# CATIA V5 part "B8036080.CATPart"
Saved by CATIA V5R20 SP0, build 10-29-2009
Part number: B8036080
Revision: 5
Definition: design
Nomenclature: B8036080
Source: made
Description: NOT SPECIFIED
Bounding box of the stored display mesh (mm): x -42.5 to 42.5, y -42.5 to 42.5, z 0 to 80
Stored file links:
  C:\Users\Utente\Desktop\3D files B803\B8036080.CATPart
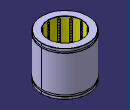
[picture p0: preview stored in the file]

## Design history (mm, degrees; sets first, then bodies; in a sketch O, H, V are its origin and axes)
Body1 "MANIFOLD_SOLID_BREP #38" (main body)
  Solid1: solid without history
Body2 "MANIFOLD_SOLID_BREP #76"
  Solid2: solid without history
Body3 "MANIFOLD_SOLID_BREP #114"
  Solid3: solid without history
Body4 "MANIFOLD_SOLID_BREP #152"
  Solid4: solid without history
Body5 "MANIFOLD_SOLID_BREP #190"
  Solid5: solid without history
Body6 "MANIFOLD_SOLID_BREP #228"
  Solid6: solid without history
Body7 "MANIFOLD_SOLID_BREP #266"
  Solid7: solid without history
Body8 "MANIFOLD_SOLID_BREP #304"
  Solid8: solid without history
Body9 "MANIFOLD_SOLID_BREP #3200"
  Solid9: solid without history
Body10 "MANIFOLD_SOLID_BREP #3238"
  Solid10: solid without history
Body11 "MANIFOLD_SOLID_BREP #3276"
  Solid11: solid without history
Body12 "MANIFOLD_SOLID_BREP #3314"
  Solid12: solid without history
Body13 "MANIFOLD_SOLID_BREP #3352"
  Solid13: solid without history
Body14 "MANIFOLD_SOLID_BREP #3390"
  Solid14: solid without history
Body15 "MANIFOLD_SOLID_BREP #3428"
  Solid15: solid without history
Body16 "MANIFOLD_SOLID_BREP #3466"
  Solid16: solid without history
Body17 "MANIFOLD_SOLID_BREP #3504"
  Solid17: solid without history
Body18 "MANIFOLD_SOLID_BREP #3542"
  Solid18: solid without history
Body19 "MANIFOLD_SOLID_BREP #3580"
  Solid19: solid without history
Body20 "MANIFOLD_SOLID_BREP #3618"
  Solid20: solid without history
Body21 "MANIFOLD_SOLID_BREP #3656"
  Solid21: solid without history
Body22 "MANIFOLD_SOLID_BREP #3694"
  Solid22: solid without history
Body23 "MANIFOLD_SOLID_BREP #3732"
  Solid23: solid without history
Body24 "MANIFOLD_SOLID_BREP #3770"
  Solid24: solid without history
Body25 "MANIFOLD_SOLID_BREP #3808"
  Solid25: solid without history
Body26 "MANIFOLD_SOLID_BREP #3846"
  Solid26: solid without history
Body27 "MANIFOLD_SOLID_BREP #3884"
  Solid27: solid without history
Body28 "MANIFOLD_SOLID_BREP #3922"
  Solid28: solid without history
Body29 "MANIFOLD_SOLID_BREP #3960"
  Solid29: solid without history
Body30 "MANIFOLD_SOLID_BREP #3998"
  Solid30: solid without history
Body31 "MANIFOLD_SOLID_BREP #4036"
  Solid31: solid without history
Body32 "MANIFOLD_SOLID_BREP #4074"
  Solid32: solid without history
Body33 "MANIFOLD_SOLID_BREP #4112"
  Solid33: solid without history
Body34 "MANIFOLD_SOLID_BREP #4150"
  Solid34: solid without history
Body35 "MANIFOLD_SOLID_BREP #4188"
  Solid35: solid without history
Body36 "MANIFOLD_SOLID_BREP #4226"
  Solid36: solid without history
Body37 "MANIFOLD_SOLID_BREP #4264"
  Solid37: solid without history
Body38 "MANIFOLD_SOLID_BREP #4302"
  Solid38: solid without history
Body39 "MANIFOLD_SOLID_BREP #4340"
  Solid39: solid without history
Body40 "MANIFOLD_SOLID_BREP #4378"
  Solid40: solid without history
Body41 "MANIFOLD_SOLID_BREP #4416"
  Solid41: solid without history
Body42 "MANIFOLD_SOLID_BREP #4454"
  Solid42: solid without history
Body43 "MANIFOLD_SOLID_BREP #4492"
  Solid43: solid without history
Body44 "MANIFOLD_SOLID_BREP #4530"
  Solid44: solid without history
Body45 "MANIFOLD_SOLID_BREP #4568"
  Solid45: solid without history
Body46 "MANIFOLD_SOLID_BREP #4606"
  Solid46: solid without history
Body47 "MANIFOLD_SOLID_BREP #4644"
  Solid47: solid without history
Body48 "MANIFOLD_SOLID_BREP #4682"
  Solid48: solid without history
Body49 "MANIFOLD_SOLID_BREP #4720"
  Solid49: solid without history
Body50 "MANIFOLD_SOLID_BREP #4758"
  Solid50: solid without history
Body51 "MANIFOLD_SOLID_BREP #4796"
  Solid51: solid without history
Body52 "MANIFOLD_SOLID_BREP #4834"
  Solid52: solid without history
Body53 "MANIFOLD_SOLID_BREP #4872"
  Solid53: solid without history
Body54 "MANIFOLD_SOLID_BREP #4910"
  Solid54: solid without history
Body55 "MANIFOLD_SOLID_BREP #4948"
  Solid55: solid without history
Body56 "MANIFOLD_SOLID_BREP #4986"
  Solid56: solid without history
Body57 "MANIFOLD_SOLID_BREP #5024"
  Solid57: solid without history
Body58 "MANIFOLD_SOLID_BREP #5062"
  Solid58: solid without history
Body59 "MANIFOLD_SOLID_BREP #5100"
  Solid59: solid without history
Body60 "MANIFOLD_SOLID_BREP #5138"
  Solid60: solid without history
Body61 "MANIFOLD_SOLID_BREP #5176"
  Solid61: solid without history
Body62 "MANIFOLD_SOLID_BREP #5214"
  Solid62: solid without history
Body63 "MANIFOLD_SOLID_BREP #5252"
  Solid63: solid without history
Body64 "MANIFOLD_SOLID_BREP #5290"
  Solid64: solid without history
Body65 "MANIFOLD_SOLID_BREP #5328"
  Solid65: solid without history
Body66 "MANIFOLD_SOLID_BREP #5366"
  Solid66: solid without history
Body67 "MANIFOLD_SOLID_BREP #5404"
  Solid67: solid without history
Body68 "MANIFOLD_SOLID_BREP #5442"
  Solid68: solid without history
Body69 "MANIFOLD_SOLID_BREP #5480"
  Solid69: solid without history
Body70 "MANIFOLD_SOLID_BREP #5518"
  Solid70: solid without history
Body71 "MANIFOLD_SOLID_BREP #5556"
  Solid71: solid without history
Body72 "MANIFOLD_SOLID_BREP #5594"
  Solid72: solid without history
Body73 "MANIFOLD_SOLID_BREP #5632"
  Solid73: solid without history
Body74 "MANIFOLD_SOLID_BREP #5670"
  Solid74: solid without history
Body75 "MANIFOLD_SOLID_BREP #5708"
  Solid75: solid without history
Body76 "MANIFOLD_SOLID_BREP #5746"
  Solid76: solid without history
Body77 "MANIFOLD_SOLID_BREP #5784"
  Solid77: solid without history
Body78 "MANIFOLD_SOLID_BREP #5822"
  Solid78: solid without history
Body79 "MANIFOLD_SOLID_BREP #5860"
  Solid79: solid without history
Body80 "MANIFOLD_SOLID_BREP #5898"
  Solid80: solid without history
Body81 "MANIFOLD_SOLID_BREP #5936"
  Solid81: solid without history
Body82 "MANIFOLD_SOLID_BREP #5974"
  Solid82: solid without history
Body83 "MANIFOLD_SOLID_BREP #6012"
  Solid83: solid without history
Body84 "MANIFOLD_SOLID_BREP #6050"
  Solid84: solid without history
Body85 "MANIFOLD_SOLID_BREP #6088"
  Solid85: solid without history
Body86 "MANIFOLD_SOLID_BREP #6126"
  Solid86: solid without history
Body87 "MANIFOLD_SOLID_BREP #6164"
  Solid87: solid without history
Body88 "MANIFOLD_SOLID_BREP #6202"
  Solid88: solid without history
Body89 "MANIFOLD_SOLID_BREP #6240"
  Solid89: solid without history
Body90 "MANIFOLD_SOLID_BREP #6278"
  Solid90: solid without history
Body91 "MANIFOLD_SOLID_BREP #6316"
  Solid91: solid without history
Body92 "MANIFOLD_SOLID_BREP #6354"
  Solid92: solid without history
Body93 "MANIFOLD_SOLID_BREP #6392"
  Solid93: solid without history
Body94 "MANIFOLD_SOLID_BREP #6430"
  Solid94: solid without history
Body95 "MANIFOLD_SOLID_BREP #6468"
  Solid95: solid without history
Body96 "MANIFOLD_SOLID_BREP #6506"
  Solid96: solid without history
Body97 "MANIFOLD_SOLID_BREP #6544"
  Solid97: solid without history
Body98 "MANIFOLD_SOLID_BREP #6582"
  Solid98: solid without history
Body99 "MANIFOLD_SOLID_BREP #6620"
  Solid99: solid without history
Body100 "MANIFOLD_SOLID_BREP #6658"
  Solid100: solid without history
Body101 "MANIFOLD_SOLID_BREP #6696"
  Solid101: solid without history
Body102 "MANIFOLD_SOLID_BREP #6734"
  Solid102: solid without history
Body103 "MANIFOLD_SOLID_BREP #6772"
  Solid103: solid without history
Body104 "MANIFOLD_SOLID_BREP #6810"
  Solid104: solid without history
Body105 "MANIFOLD_SOLID_BREP #6848"
  Solid105: solid without history
Body106 "MANIFOLD_SOLID_BREP #6886"
  Solid106: solid without history
Body107 "MANIFOLD_SOLID_BREP #6924"
  Solid107: solid without history
Body108 "MANIFOLD_SOLID_BREP #6962"
  Solid108: solid without history
Body109 "MANIFOLD_SOLID_BREP #7000"
  Solid109: solid without history
Body110 "MANIFOLD_SOLID_BREP #7038"
  Solid110: solid without history
Body111 "MANIFOLD_SOLID_BREP #7076"
  Solid111: solid without history
Body112 "MANIFOLD_SOLID_BREP #7114"
  Solid112: solid without history
Body113 "MANIFOLD_SOLID_BREP #7152"
  Solid113: solid without history
Body114 "MANIFOLD_SOLID_BREP #7190"
  Solid114: solid without history
Body115 "MANIFOLD_SOLID_BREP #7228"
  Solid115: solid without history
Body116 "MANIFOLD_SOLID_BREP #7266"
  Solid116: solid without history
Body117 "MANIFOLD_SOLID_BREP #7304"
  Solid117: solid without history
Body118 "MANIFOLD_SOLID_BREP #7342"
  Solid118: solid without history
Body119 "MANIFOLD_SOLID_BREP #7380"
  Solid119: solid without history
Body120 "MANIFOLD_SOLID_BREP #7418"
  Solid120: solid without history
Body121 "MANIFOLD_SOLID_BREP #7456"
  Solid121: solid without history
Body122 "MANIFOLD_SOLID_BREP #7494"
  Solid122: solid without history
Body123 "MANIFOLD_SOLID_BREP #7532"
  Solid123: solid without history
Body124 "MANIFOLD_SOLID_BREP #7570"
  Solid124: solid without history
Body125 "MANIFOLD_SOLID_BREP #7608"
  Solid125: solid without history
Body126 "MANIFOLD_SOLID_BREP #7646"
  Solid126: solid without history
Body127 "MANIFOLD_SOLID_BREP #7684"
  Solid127: solid without history
Body128 "MANIFOLD_SOLID_BREP #7722"
  Solid128: solid without history
Body129 "MANIFOLD_SOLID_BREP #7760"
  Solid129: solid without history
Body130 "MANIFOLD_SOLID_BREP #7798"
  Solid130: solid without history
Body131 "MANIFOLD_SOLID_BREP #7836"
  Solid131: solid without history
Body132 "MANIFOLD_SOLID_BREP #7874"
  Solid132: solid without history
Body133 "MANIFOLD_SOLID_BREP #7912"
  Solid133: solid without history
Body134 "MANIFOLD_SOLID_BREP #7950"
  Solid134: solid without history
Body135 "MANIFOLD_SOLID_BREP #7988"
  Solid135: solid without history
Body136 "MANIFOLD_SOLID_BREP #8026"
  Solid136: solid without history
Body137 "MANIFOLD_SOLID_BREP #8064"
  Solid137: solid without history
Body138 "MANIFOLD_SOLID_BREP #8102"
  Solid138: solid without history
Body139 "MANIFOLD_SOLID_BREP #8140"
  Solid139: solid without history
Body140 "MANIFOLD_SOLID_BREP #8178"
  Solid140: solid without history
Body141 "MANIFOLD_SOLID_BREP #8216"
  Solid141: solid without history
Body142 "MANIFOLD_SOLID_BREP #8254"
  Solid142: solid without history
Body143 "MANIFOLD_SOLID_BREP #8292"
  Solid143: solid without history
Body144 "MANIFOLD_SOLID_BREP #8330"
  Solid144: solid without history
Body145 "MANIFOLD_SOLID_BREP #8368"
  Solid145: solid without history
Body146 "MANIFOLD_SOLID_BREP #8406"
  Solid146: solid without history
Body147 "MANIFOLD_SOLID_BREP #8444"
  Solid147: solid without history
Body148 "MANIFOLD_SOLID_BREP #8482"
  Solid148: solid without history
Body149 "MANIFOLD_SOLID_BREP #8520"
  Solid149: solid without history
Body150 "MANIFOLD_SOLID_BREP #8558"
  Solid150: solid without history
Body151 "MANIFOLD_SOLID_BREP #8596"
  Solid151: solid without history
Body152 "MANIFOLD_SOLID_BREP #8634"
  Solid152: solid without history
Body153 "MANIFOLD_SOLID_BREP #8672"
  Solid153: solid without history
Body154 "MANIFOLD_SOLID_BREP #8710"
  Solid154: solid without history
Body155 "MANIFOLD_SOLID_BREP #8748"
  Solid155: solid without history
Body156 "MANIFOLD_SOLID_BREP #8786"
  Solid156: solid without history
Body157 "MANIFOLD_SOLID_BREP #8824"
  Solid157: solid without history
Body158 "MANIFOLD_SOLID_BREP #8862"
  Solid158: solid without history
Body159 "MANIFOLD_SOLID_BREP #8900"
  Solid159: solid without history
Body160 "MANIFOLD_SOLID_BREP #8938"
  Solid160: solid without history
Body161 "MANIFOLD_SOLID_BREP #8976"
  Solid161: solid without history
Body162 "MANIFOLD_SOLID_BREP #9014"
  Solid162: solid without history
Body163 "MANIFOLD_SOLID_BREP #9052"
  Solid163: solid without history
Body164 "MANIFOLD_SOLID_BREP #9090"
  Solid164: solid without history
Body165 "MANIFOLD_SOLID_BREP #9128"
  Solid165: solid without history
Body166 "MANIFOLD_SOLID_BREP #9166"
  Solid166: solid without history
Body167 "MANIFOLD_SOLID_BREP #9204"
  Solid167: solid without history
Body168 "MANIFOLD_SOLID_BREP #9242"
  Solid168: solid without history
Body169 "MANIFOLD_SOLID_BREP #9280"
  Solid169: solid without history
Body170 "MANIFOLD_SOLID_BREP #9318"
  Solid170: solid without history
Body171 "MANIFOLD_SOLID_BREP #9356"
  Solid171: solid without history
Body172 "MANIFOLD_SOLID_BREP #9394"
  Solid172: solid without history
Body173 "MANIFOLD_SOLID_BREP #9432"
  Solid173: solid without history
Body174 "MANIFOLD_SOLID_BREP #9470"
  Solid174: solid without history
Body175 "MANIFOLD_SOLID_BREP #9508"
  Solid175: solid without history
Body176 "MANIFOLD_SOLID_BREP #9546"
  Solid176: solid without history
Body177 "MANIFOLD_SOLID_BREP #9584"
  Solid177: solid without history
Body178 "MANIFOLD_SOLID_BREP #9622"
  Solid178: solid without history
Body179 "MANIFOLD_SOLID_BREP #9660"
  Solid179: solid without history
Body180 "MANIFOLD_SOLID_BREP #9698"
  Solid180: solid without history
Body181 "MANIFOLD_SOLID_BREP #9736"
  Solid181: solid without history
Body182 "MANIFOLD_SOLID_BREP #9774"
  Solid182: solid without history
Body183 "MANIFOLD_SOLID_BREP #9812"
  Solid183: solid without history
Body184 "MANIFOLD_SOLID_BREP #9850"
  Solid184: solid without history
Body185 "MANIFOLD_SOLID_BREP #9888"
  Solid185: solid without history
Body186 "MANIFOLD_SOLID_BREP #9926"
  Solid186: solid without history
Body187 "MANIFOLD_SOLID_BREP #9964"
  Solid187: solid without history
Body188 "MANIFOLD_SOLID_BREP #10002"
  Solid188: solid without history
Body189 "MANIFOLD_SOLID_BREP #10040"
  Solid189: solid without history
Body190 "MANIFOLD_SOLID_BREP #10078"
  Solid190: solid without history
Body191 "MANIFOLD_SOLID_BREP #10116"
  Solid191: solid without history
Body192 "MANIFOLD_SOLID_BREP #10154"
  Solid192: solid without history
Body193 "MANIFOLD_SOLID_BREP #10192"
  Solid193: solid without history
Body194 "MANIFOLD_SOLID_BREP #10230"
  Solid194: solid without history
Body195 "MANIFOLD_SOLID_BREP #10268"
  Solid195: solid without history
Body196 "MANIFOLD_SOLID_BREP #10306"
  Solid196: solid without history
Body197 "MANIFOLD_SOLID_BREP #10344"
  Solid197: solid without history
Body198 "MANIFOLD_SOLID_BREP #10382"
  Solid198: solid without history
Body199 "MANIFOLD_SOLID_BREP #10420"
  Solid199: solid without history
Body200 "MANIFOLD_SOLID_BREP #10458"
  Solid200: solid without history
Body201 "MANIFOLD_SOLID_BREP #10496"
  Solid201: solid without history
Body202 "MANIFOLD_SOLID_BREP #10534"
  Solid202: solid without history
Body203 "MANIFOLD_SOLID_BREP #10572"
  Solid203: solid without history
Body204 "MANIFOLD_SOLID_BREP #10610"
  Solid204: solid without history
Body205 "MANIFOLD_SOLID_BREP #10648"
  Solid205: solid without history
Body206 "MANIFOLD_SOLID_BREP #10686"
  Solid206: solid without history
Body207 "MANIFOLD_SOLID_BREP #10724"
  Solid207: solid without history
Body208 "MANIFOLD_SOLID_BREP #10762"
  Solid208: solid without history
Body209 "MANIFOLD_SOLID_BREP #10800"
  Solid209: solid without history
Body210 "MANIFOLD_SOLID_BREP #10838"
  Solid210: solid without history
Body211 "MANIFOLD_SOLID_BREP #10876"
  Solid211: solid without history
Body212 "MANIFOLD_SOLID_BREP #10914"
  Solid212: solid without history
Body213 "MANIFOLD_SOLID_BREP #10952"
  Solid213: solid without history
Body214 "MANIFOLD_SOLID_BREP #10990"
  Solid214: solid without history
Body215 "MANIFOLD_SOLID_BREP #11028"
  Solid215: solid without history
Body216 "MANIFOLD_SOLID_BREP #11066"
  Solid216: solid without history
Body217 "MANIFOLD_SOLID_BREP #11104"
  Solid217: solid without history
